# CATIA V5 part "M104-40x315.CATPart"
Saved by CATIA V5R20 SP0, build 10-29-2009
Part number: M104-40x315
Source: Unknown
Bounding box of the stored display mesh (mm): x -19.994 to 19.994, y -19.994 to 19.994, z 0 to 315
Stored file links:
  C:\Users\Utente\Desktop\IO LAVORO\3D X SITO CF\X SITO\M104\M104-40x315.CATPart

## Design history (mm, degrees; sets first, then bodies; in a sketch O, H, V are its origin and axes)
Body1 (main body)
  Solid1 "PartBody": solid without history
